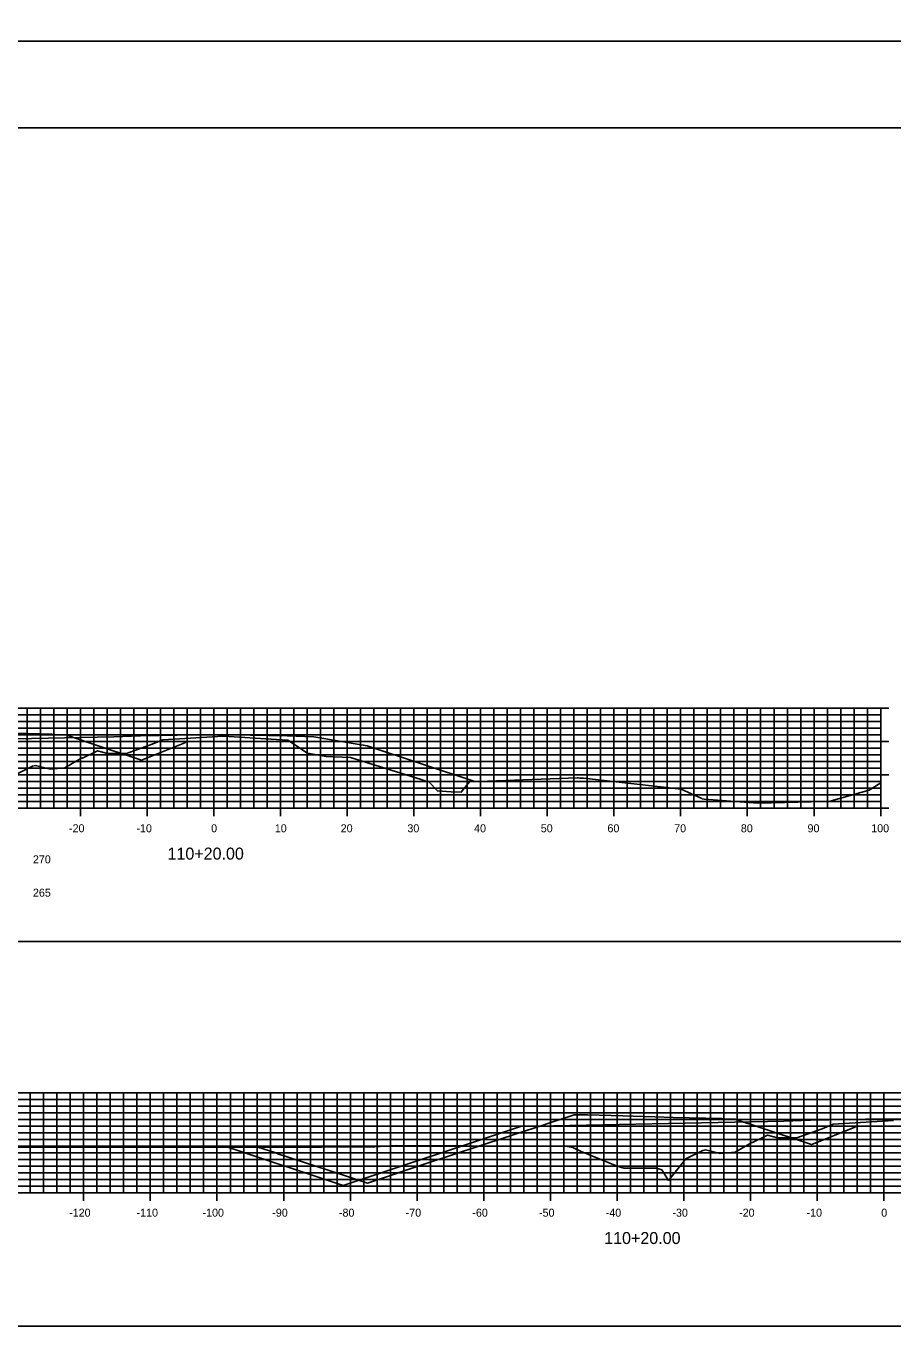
# Model space of a CAD drawing. Extents: x 1661012 to 1662122, y 670053 to 671852.
# Drawn here: x 1661778.9 to 1661908.9, y 671480 to 671675 of the extents above; entities that cross this region are included whole.
import ezdxf

# ---------------------------------------------------------------- set-up
doc = ezdxf.new("R2010")
doc.units = 0
for name, color, linetype in [('R_Concrete', 7, 'Continuous'), ('R_Concrete Hidden', 7, 'Continuous'), ('R_Erosion', 7, 'Continuous'), ('R_Exist Surface', 7, 'Continuous'), ('R_Proposed Road', 7, 'Continuous'), ('R_ROW Annot', 7, 'Continuous')]:
    doc.layers.add(name, color=color, linetype=linetype)

msp = doc.modelspace()

# ---------------------------------------------------------------- linework, layer by layer
at = {"layer": 'R_Concrete'}
for p, q in [((1661707.02, 671572.62), (1661907.02, 671572.62)), ((1661707.02, 671571.62), (1661907.02, 671571.62)), ((1661779.02, 671557.62), (1661779.02, 671572.62)), ((1661781.02, 671557.62), (1661781.02, 671572.62)), ((1661783.02, 671557.62), (1661783.02, 671572.62)), ((1661785.02, 671557.62), (1661785.02, 671572.62)), ((1661787.02, 671557.62), (1661787.02, 671572.62)), ((1661789.02, 671557.62), (1661789.02, 671572.62)), ((1661791.02, 671557.62), (1661791.02, 671572.62)), ((1661793.02, 671557.62), (1661793.02, 671572.62)), ((1661795.02, 671557.62), (1661795.02, 671572.62)), ((1661797.02, 671557.62), (1661797.02, 671572.62)), ((1661799.02, 671557.62), (1661799.02, 671572.62)), ((1661801.02, 671557.62), (1661801.02, 671572.62)), ((1661803.02, 671557.62), (1661803.02, 671572.62)), ((1661805.02, 671557.62), (1661805.02, 671572.62)), ((1661807.02, 671557.62), (1661807.02, 671572.62)), ((1661809.02, 671557.62), (1661809.02, 671572.62)), ((1661811.02, 671557.62), (1661811.02, 671572.62)), ((1661813.02, 671557.62), (1661813.02, 671572.62)), ((1661815.02, 671557.62), (1661815.02, 671572.62)), ((1661817.02, 671557.62), (1661817.02, 671572.62)), ((1661819.02, 671557.62), (1661819.02, 671572.62)), ((1661821.02, 671557.62), (1661821.02, 671572.62)), ((1661823.02, 671557.62), (1661823.02, 671572.62)), ((1661825.02, 671557.62), (1661825.02, 671572.62)), ((1661827.02, 671557.62), (1661827.02, 671572.62)), ((1661829.02, 671557.62), (1661829.02, 671572.62)), ((1661831.02, 671557.62), (1661831.02, 671572.62)), ((1661833.02, 671557.62), (1661833.02, 671572.62)), ((1661835.02, 671557.62), (1661835.02, 671572.62)), ((1661837.02, 671557.62), (1661837.02, 671572.62)), ((1661839.02, 671557.62), (1661839.02, 671572.62)), ((1661841.02, 671557.62), (1661841.02, 671572.62)), ((1661843.02, 671557.62), (1661843.02, 671572.62)), ((1661845.02, 671557.62), (1661845.02, 671572.62)), ((1661847.02, 671557.62), (1661847.02, 671572.62)), ((1661849.02, 671557.62), (1661849.02, 671572.62)), ((1661851.02, 671557.62), (1661851.02, 671572.62)), ((1661853.02, 671557.62), (1661853.02, 671572.62)), ((1661855.02, 671557.62), (1661855.02, 671572.62)), ((1661857.02, 671557.62), (1661857.02, 671572.62)), ((1661859.02, 671557.62), (1661859.02, 671572.62)), ((1661861.02, 671557.62), (1661861.02, 671572.62)), ((1661863.02, 671557.62), (1661863.02, 671572.62)), ((1661865.02, 671557.62), (1661865.02, 671572.62)), ((1661867.02, 671557.62), (1661867.02, 671572.62)), ((1661869.02, 671557.62), (1661869.02, 671572.62)), ((1661871.02, 671557.62), (1661871.02, 671572.62)), ((1661873.02, 671557.62), (1661873.02, 671572.62)), ((1661875.02, 671557.62), (1661875.02, 671572.62)), ((1661877.02, 671557.62), (1661877.02, 671572.62)), ((1661879.02, 671557.62), (1661879.02, 671572.62)), ((1661881.02, 671557.62), (1661881.02, 671572.62)), ((1661883.02, 671557.62), (1661883.02, 671572.62)), ((1661885.02, 671557.62), (1661885.02, 671572.62)), ((1661887.02, 671557.62), (1661887.02, 671572.62)), ((1661889.02, 671557.62), (1661889.02, 671572.62)), ((1661891.02, 671557.62), (1661891.02, 671572.62)), ((1661893.02, 671557.62), (1661893.02, 671572.62)), ((1661895.02, 671557.62), (1661895.02, 671572.62)), ((1661897.02, 671557.62), (1661897.02, 671572.62)), ((1661899.02, 671557.62), (1661899.02, 671572.62)), ((1661901.02, 671557.62), (1661901.02, 671572.62)), ((1661903.02, 671557.62), (1661903.02, 671572.62)), ((1661905.02, 671557.62), (1661905.02, 671572.62)), ((1661908.22, 671572.62), (1661905.82, 671572.62)), ((1661907.02, 671571.62), (1661906.42, 671571.62)), ((1661907.02, 671557.62), (1661907.02, 671572.62)), ((1661707.02, 671570.62), (1661907.02, 671570.62)), ((1661707.02, 671569.62), (1661907.02, 671569.62)), ((1661907.02, 671570.62), (1661906.42, 671570.62)), ((1661907.02, 671569.62), (1661906.42, 671569.62)), ((1661707.02, 671568.62), (1661907.02, 671568.62)), ((1661707.02, 671567.62), (1661907.02, 671567.62)), ((1661908.22, 671567.62), (1661905.82, 671567.62)), ((1661907.02, 671568.62), (1661906.42, 671568.62)), ((1661707.02, 671566.62), (1661907.02, 671566.62)), ((1661707.02, 671565.62), (1661907.02, 671565.62)), ((1661907.02, 671566.62), (1661906.42, 671566.62)), ((1661907.02, 671565.62), (1661906.42, 671565.62)), ((1661707.02, 671564.62), (1661907.02, 671564.62)), ((1661707.02, 671563.62), (1661907.02, 671563.62)), ((1661907.02, 671564.62), (1661906.42, 671564.62)), ((1661907.02, 671563.62), (1661906.42, 671563.62)), ((1661707.02, 671562.62), (1661907.02, 671562.62)), ((1661707.02, 671561.62), (1661907.02, 671561.62)), ((1661908.22, 671562.62), (1661905.82, 671562.62)), ((1661907.02, 671561.62), (1661906.42, 671561.62)), ((1661707.02, 671560.62), (1661907.02, 671560.62)), ((1661707.02, 671559.62), (1661907.02, 671559.62)), ((1661907.02, 671560.62), (1661906.42, 671560.62)), ((1661907.02, 671559.62), (1661906.42, 671559.62)), ((1661707.02, 671558.62), (1661907.02, 671558.62)), ((1661707.02, 671557.62), (1661907.02, 671557.62)), ((1661779.02, 671557.62), (1661779.02, 671558.22)), ((1661781.02, 671557.62), (1661781.02, 671558.22)), ((1661783.02, 671557.62), (1661783.02, 671558.22)), ((1661785.02, 671557.62), (1661785.02, 671558.22)), ((1661787.02, 671556.42), (1661787.02, 671558.82)), ((1661789.02, 671557.62), (1661789.02, 671558.22)), ((1661791.02, 671557.62), (1661791.02, 671558.22)), ((1661793.02, 671557.62), (1661793.02, 671558.22)), ((1661795.02, 671557.62), (1661795.02, 671558.22)), ((1661797.02, 671556.42), (1661797.02, 671558.82)), ((1661799.02, 671557.62), (1661799.02, 671558.22)), ((1661801.02, 671557.62), (1661801.02, 671558.22)), ((1661803.02, 671557.62), (1661803.02, 671558.22)), ((1661805.02, 671557.62), (1661805.02, 671558.22)), ((1661807.02, 671556.42), (1661807.02, 671558.82)), ((1661809.02, 671557.62), (1661809.02, 671558.22)), ((1661811.02, 671557.62), (1661811.02, 671558.22)), ((1661813.02, 671557.62), (1661813.02, 671558.22)), ((1661815.02, 671557.62), (1661815.02, 671558.22)), ((1661817.02, 671556.42), (1661817.02, 671558.82)), ((1661819.02, 671557.62), (1661819.02, 671558.22)), ((1661821.02, 671557.62), (1661821.02, 671558.22)), ((1661823.02, 671557.62), (1661823.02, 671558.22)), ((1661825.02, 671557.62), (1661825.02, 671558.22)), ((1661827.02, 671556.42), (1661827.02, 671558.82)), ((1661829.02, 671557.62), (1661829.02, 671558.22)), ((1661831.02, 671557.62), (1661831.02, 671558.22)), ((1661833.02, 671557.62), (1661833.02, 671558.22)), ((1661835.02, 671557.62), (1661835.02, 671558.22)), ((1661837.02, 671556.42), (1661837.02, 671558.82)), ((1661839.02, 671557.62), (1661839.02, 671558.22)), ((1661841.02, 671557.62), (1661841.02, 671558.22)), ((1661843.02, 671557.62), (1661843.02, 671558.22)), ((1661845.02, 671557.62), (1661845.02, 671558.22)), ((1661847.02, 671556.42), (1661847.02, 671558.82)), ((1661849.02, 671557.62), (1661849.02, 671558.22)), ((1661851.02, 671557.62), (1661851.02, 671558.22)), ((1661853.02, 671557.62), (1661853.02, 671558.22)), ((1661855.02, 671557.62), (1661855.02, 671558.22)), ((1661857.02, 671556.42), (1661857.02, 671558.82)), ((1661859.02, 671557.62), (1661859.02, 671558.22)), ((1661861.02, 671557.62), (1661861.02, 671558.22)), ((1661863.02, 671557.62), (1661863.02, 671558.22)), ((1661865.02, 671557.62), (1661865.02, 671558.22)), ((1661867.02, 671556.42), (1661867.02, 671558.82)), ((1661869.02, 671557.62), (1661869.02, 671558.22)), ((1661871.02, 671557.62), (1661871.02, 671558.22)), ((1661873.02, 671557.62), (1661873.02, 671558.22)), ((1661875.02, 671557.62), (1661875.02, 671558.22)), ((1661877.02, 671556.42), (1661877.02, 671558.82)), ((1661879.02, 671557.62), (1661879.02, 671558.22)), ((1661881.02, 671557.62), (1661881.02, 671558.22)), ((1661883.02, 671557.62), (1661883.02, 671558.22)), ((1661885.02, 671557.62), (1661885.02, 671558.22)), ((1661887.02, 671556.42), (1661887.02, 671558.82)), ((1661889.02, 671557.62), (1661889.02, 671558.22)), ((1661891.02, 671557.62), (1661891.02, 671558.22)), ((1661893.02, 671557.62), (1661893.02, 671558.22)), ((1661895.02, 671557.62), (1661895.02, 671558.22)), ((1661897.02, 671556.42), (1661897.02, 671558.82)), ((1661899.02, 671557.62), (1661899.02, 671558.22)), ((1661901.02, 671557.62), (1661901.02, 671558.22)), ((1661903.02, 671557.62), (1661903.02, 671558.22)), ((1661905.02, 671557.62), (1661905.02, 671558.22)), ((1661908.22, 671557.62), (1661905.82, 671557.62)), ((1661907.02, 671558.62), (1661906.42, 671558.62)), ((1661907.02, 671556.42), (1661907.02, 671558.82)), ((1661707.5, 671514.96), (1662037.5, 671514.96)), ((1661779.5, 671499.96), (1661779.5, 671514.96)), ((1661781.5, 671499.96), (1661781.5, 671514.96)), ((1661783.5, 671499.96), (1661783.5, 671514.96)), ((1661785.5, 671499.96), (1661785.5, 671514.96)), ((1661787.5, 671499.96), (1661787.5, 671514.96)), ((1661789.5, 671499.96), (1661789.5, 671514.96)), ((1661791.5, 671499.96), (1661791.5, 671514.96)), ((1661793.5, 671499.96), (1661793.5, 671514.96)), ((1661795.5, 671499.96), (1661795.5, 671514.96)), ((1661797.5, 671499.96), (1661797.5, 671514.96)), ((1661799.5, 671499.96), (1661799.5, 671514.96)), ((1661801.5, 671499.96), (1661801.5, 671514.96)), ((1661803.5, 671499.96), (1661803.5, 671514.96)), ((1661805.5, 671499.96), (1661805.5, 671514.96)), ((1661807.5, 671499.96), (1661807.5, 671514.96)), ((1661809.5, 671499.96), (1661809.5, 671514.96)), ((1661811.5, 671499.96), (1661811.5, 671514.96)), ((1661813.5, 671499.96), (1661813.5, 671514.96)), ((1661815.5, 671499.96), (1661815.5, 671514.96)), ((1661817.5, 671499.96), (1661817.5, 671514.96)), ((1661819.5, 671499.96), (1661819.5, 671514.96)), ((1661821.5, 671499.96), (1661821.5, 671514.96)), ((1661823.5, 671499.96), (1661823.5, 671514.96)), ((1661825.5, 671499.96), (1661825.5, 671514.96)), ((1661827.5, 671499.96), (1661827.5, 671514.96)), ((1661829.5, 671499.96), (1661829.5, 671514.96)), ((1661831.5, 671499.96), (1661831.5, 671514.96)), ((1661833.5, 671499.96), (1661833.5, 671514.96)), ((1661835.5, 671499.96), (1661835.5, 671514.96)), ((1661837.5, 671499.96), (1661837.5, 671514.96)), ((1661839.5, 671499.96), (1661839.5, 671514.96)), ((1661841.5, 671499.96), (1661841.5, 671514.96)), ((1661843.5, 671499.96), (1661843.5, 671514.96)), ((1661845.5, 671499.96), (1661845.5, 671514.96)), ((1661847.5, 671499.96), (1661847.5, 671514.96)), ((1661849.5, 671499.96), (1661849.5, 671514.96)), ((1661851.5, 671499.96), (1661851.5, 671514.96)), ((1661853.5, 671499.96), (1661853.5, 671514.96)), ((1661855.5, 671499.96), (1661855.5, 671514.96)), ((1661857.5, 671499.96), (1661857.5, 671514.96)), ((1661859.5, 671499.96), (1661859.5, 671514.96)), ((1661861.5, 671499.96), (1661861.5, 671514.96)), ((1661863.5, 671499.96), (1661863.5, 671514.96)), ((1661865.5, 671499.96), (1661865.5, 671514.96)), ((1661867.5, 671499.96), (1661867.5, 671514.96)), ((1661869.5, 671499.96), (1661869.5, 671514.96)), ((1661871.5, 671499.96), (1661871.5, 671514.96)), ((1661873.5, 671499.96), (1661873.5, 671514.96)), ((1661875.5, 671499.96), (1661875.5, 671514.96)), ((1661877.5, 671499.96), (1661877.5, 671514.96)), ((1661879.5, 671499.96), (1661879.5, 671514.96)), ((1661881.5, 671499.96), (1661881.5, 671514.96)), ((1661883.5, 671499.96), (1661883.5, 671514.96)), ((1661885.5, 671499.96), (1661885.5, 671514.96)), ((1661887.5, 671499.96), (1661887.5, 671514.96)), ((1661889.5, 671499.96), (1661889.5, 671514.96)), ((1661891.5, 671499.96), (1661891.5, 671514.96)), ((1661893.5, 671499.96), (1661893.5, 671514.96)), ((1661895.5, 671499.96), (1661895.5, 671514.96)), ((1661897.5, 671499.96), (1661897.5, 671514.96)), ((1661899.5, 671499.96), (1661899.5, 671514.96)), ((1661901.5, 671499.96), (1661901.5, 671514.96)), ((1661903.5, 671499.96), (1661903.5, 671514.96)), ((1661905.5, 671499.96), (1661905.5, 671514.96)), ((1661907.5, 671499.96), (1661907.5, 671514.96)), ((1661707.5, 671513.96), (1662037.5, 671513.96)), ((1661707.5, 671512.96), (1662037.5, 671512.96)), ((1661707.5, 671511.96), (1662037.5, 671511.96)), ((1661707.5, 671510.96), (1662037.5, 671510.96)), ((1661707.5, 671509.96), (1662037.5, 671509.96)), ((1661707.5, 671508.96), (1662037.5, 671508.96)), ((1661707.5, 671507.96), (1662037.5, 671507.96)), ((1661707.5, 671506.96), (1662037.5, 671506.96)), ((1661707.5, 671505.96), (1662037.5, 671505.96)), ((1661707.5, 671504.96), (1662037.5, 671504.96)), ((1661707.5, 671503.96), (1662037.5, 671503.96)), ((1661707.5, 671502.96), (1662037.5, 671502.96)), ((1661707.5, 671501.96), (1662037.5, 671501.96)), ((1661707.5, 671500.96), (1662037.5, 671500.96)), ((1661779.5, 671499.96), (1661779.5, 671500.56)), ((1661781.5, 671499.96), (1661781.5, 671500.56)), ((1661783.5, 671499.96), (1661783.5, 671500.56)), ((1661785.5, 671499.96), (1661785.5, 671500.56)), ((1661787.5, 671498.76), (1661787.5, 671501.16)), ((1661789.5, 671499.96), (1661789.5, 671500.56)), ((1661791.5, 671499.96), (1661791.5, 671500.56)), ((1661793.5, 671499.96), (1661793.5, 671500.56)), ((1661795.5, 671499.96), (1661795.5, 671500.56)), ((1661797.5, 671498.76), (1661797.5, 671501.16)), ((1661799.5, 671499.96), (1661799.5, 671500.56)), ((1661801.5, 671499.96), (1661801.5, 671500.56)), ((1661803.5, 671499.96), (1661803.5, 671500.56)), ((1661805.5, 671499.96), (1661805.5, 671500.56)), ((1661807.5, 671498.76), (1661807.5, 671501.16)), ((1661809.5, 671499.96), (1661809.5, 671500.56)), ((1661811.5, 671499.96), (1661811.5, 671500.56)), ((1661813.5, 671499.96), (1661813.5, 671500.56)), ((1661815.5, 671499.96), (1661815.5, 671500.56)), ((1661817.5, 671498.76), (1661817.5, 671501.16)), ((1661819.5, 671499.96), (1661819.5, 671500.56)), ((1661821.5, 671499.96), (1661821.5, 671500.56)), ((1661823.5, 671499.96), (1661823.5, 671500.56)), ((1661825.5, 671499.96), (1661825.5, 671500.56)), ((1661827.5, 671498.76), (1661827.5, 671501.16)), ((1661829.5, 671499.96), (1661829.5, 671500.56)), ((1661831.5, 671499.96), (1661831.5, 671500.56)), ((1661833.5, 671499.96), (1661833.5, 671500.56)), ((1661835.5, 671499.96), (1661835.5, 671500.56)), ((1661837.5, 671498.76), (1661837.5, 671501.16)), ((1661839.5, 671499.96), (1661839.5, 671500.56)), ((1661841.5, 671499.96), (1661841.5, 671500.56)), ((1661843.5, 671499.96), (1661843.5, 671500.56)), ((1661845.5, 671499.96), (1661845.5, 671500.56)), ((1661847.5, 671498.76), (1661847.5, 671501.16)), ((1661849.5, 671499.96), (1661849.5, 671500.56)), ((1661851.5, 671499.96), (1661851.5, 671500.56)), ((1661853.5, 671499.96), (1661853.5, 671500.56)), ((1661855.5, 671499.96), (1661855.5, 671500.56)), ((1661857.5, 671498.76), (1661857.5, 671501.16)), ((1661859.5, 671499.96), (1661859.5, 671500.56)), ((1661861.5, 671499.96), (1661861.5, 671500.56)), ((1661863.5, 671499.96), (1661863.5, 671500.56)), ((1661865.5, 671499.96), (1661865.5, 671500.56)), ((1661867.5, 671498.76), (1661867.5, 671501.16)), ((1661869.5, 671499.96), (1661869.5, 671500.56)), ((1661871.5, 671499.96), (1661871.5, 671500.56)), ((1661873.5, 671499.96), (1661873.5, 671500.56)), ((1661875.5, 671499.96), (1661875.5, 671500.56)), ((1661877.5, 671498.76), (1661877.5, 671501.16)), ((1661879.5, 671499.96), (1661879.5, 671500.56)), ((1661881.5, 671499.96), (1661881.5, 671500.56)), ((1661883.5, 671499.96), (1661883.5, 671500.56)), ((1661885.5, 671499.96), (1661885.5, 671500.56)), ((1661887.5, 671498.76), (1661887.5, 671501.16)), ((1661889.5, 671499.96), (1661889.5, 671500.56)), ((1661891.5, 671499.96), (1661891.5, 671500.56)), ((1661893.5, 671499.96), (1661893.5, 671500.56)), ((1661895.5, 671499.96), (1661895.5, 671500.56)), ((1661897.5, 671498.76), (1661897.5, 671501.16)), ((1661899.5, 671499.96), (1661899.5, 671500.56)), ((1661901.5, 671499.96), (1661901.5, 671500.56)), ((1661903.5, 671499.96), (1661903.5, 671500.56)), ((1661905.5, 671499.96), (1661905.5, 671500.56)), ((1661907.5, 671498.76), (1661907.5, 671501.16)), ((1661707.5, 671499.96), (1662037.5, 671499.96))]:
    msp.add_line(p, q, dxfattribs=at)
at = {"layer": 'R_Erosion'}
for points in [[(1661777.32, 671562.7), (1661779.85, 671563.96), (1661780.28, 671564.03), (1661782.47, 671563.49), (1661784.7, 671563.71), (1661787.23, 671565.17), (1661787.32, 671565.16), (1661789.56, 671566.25), (1661791.09, 671565.85), (1661793.94, 671565.85), (1661797.79, 671567.22), (1661799.4, 671567.9), (1661808.46, 671568.46), (1661816.44, 671567.94), (1661818.14, 671567.82), (1661821.05, 671565.89), (1661823.86, 671565.41), (1661827.47, 671565.25), (1661827.5, 671565.23), (1661838.1, 671561.92), (1661838.93, 671561.65), (1661839.23, 671561.58), (1661839.24, 671561.57), (1661840.56, 671560.23), (1661842.63, 671560.11), (1661844.12, 671560.06), (1661844.93, 671561.03), (1661845.38, 671561.6), (1661861.51, 671562.19), (1661861.65, 671562.21), (1661861.93, 671562.16), (1661862.47, 671562.13), (1661877.08, 671560.49), (1661880.18, 671559.07), (1661880.25, 671559.03), (1661880.53, 671559.01), (1661888.61, 671558.39), (1661898.61, 671558.64), (1661899.28, 671558.66), (1661899.95, 671558.83), (1661905.27, 671560.32), (1661907.02, 671561.44)], [(1661767.07, 671506.79), (1661782.62, 671506.79), (1661791.52, 671506.8), (1661800.94, 671506.8), (1661814.49, 671506.8), (1661823.2, 671506.8), (1661831.18, 671506.86), (1661834.38, 671507.04), (1661855.17, 671506.94), (1661859.78, 671506.94), (1661860.88, 671506.74), (1661862.12, 671506.14), (1661867.51, 671503.95), (1661868.5, 671503.63), (1661873.42, 671503.64), (1661874.19, 671503.4), (1661875.2, 671501.81), (1661877.79, 671505.04), (1661880.33, 671506.3), (1661880.75, 671506.37), (1661882.94, 671505.83), (1661885.18, 671506.05), (1661887.71, 671507.51), (1661887.79, 671507.5), (1661890.03, 671508.59), (1661891.56, 671508.19), (1661894.42, 671508.19), (1661898.26, 671509.55), (1661899.87, 671510.24), (1661908.94, 671510.8)]]:
    msp.add_lwpolyline(points, dxfattribs=at)
at = {"layer": 'R_Exist Surface'}
for p, q in [((1661907.02, 671557.62), (1661907.02, 671572.62)), ((1661707.02, 671557.62), (1661907.02, 671557.62)), ((1661707.5, 671499.96), (1662037.5, 671499.96))]:
    msp.add_line(p, q, dxfattribs=at)
at = {"layer": 'R_Proposed Road'}
for points in [[(1661756.99, 671659.7), (1662116.99, 671659.7), (1662116.99, 671852.4), (1661756.99, 671852.4)], [(1661677.02, 671537.62), (1662037.02, 671537.62), (1662037.02, 671730.32), (1661677.02, 671730.32)], [(1661677.5, 671479.96), (1662037.5, 671479.96), (1662037.5, 671672.66), (1661677.5, 671672.66)]]:
    msp.add_lwpolyline(points, close=True, dxfattribs=at)
at = {"layer": 'R_ROW Annot'}
for points in [[(1661775.41, 671568.92), (1661782.71, 671568.73), (1661782.74, 671568.73), (1661783.17, 671568.71), (1661784.73, 671568.65), (1661784.98, 671568.57), (1661788.47, 671567.41), (1661790.14, 671566.86), (1661794.81, 671565.31), (1661796.17, 671564.86), (1661796.19, 671564.85), (1661802.66, 671567.46), (1661802.81, 671567.55)], [(1661708.63, 671564.46), (1661725.96, 671558.68), (1661752.52, 671567.54), (1661784.62, 671568.18), (1661792.02, 671568.33), (1661796.02, 671568.49), (1661807.02, 671568.71), (1661818.02, 671568.49), (1661822.02, 671568.33), (1661829.43, 671567.1), (1661830.02, 671567), (1661846.15, 671561.62)], [(1661809.1, 671506.8), (1661826.43, 671501.02), (1661853, 671509.88), (1661885.09, 671510.52), (1661892.5, 671510.67), (1661896.5, 671510.83), (1661907.5, 671511.05), (1661918.5, 671510.83), (1661922.5, 671510.67), (1661929.91, 671509.43), (1661930.5, 671509.34), (1661946.62, 671503.96)], [(1661813.63, 671506.8), (1661816.16, 671505.97), (1661816.64, 671505.81), (1661826.15, 671502.68), (1661830.05, 671501.4), (1661838.88, 671504.32), (1661850.99, 671508.32), (1661851.21, 671508.39), (1661852.36, 671508.77), (1661856.41, 671510.11), (1661857.13, 671510.35), (1661860.16, 671511.35), (1661861.05, 671511.64), (1661861.61, 671511.64), (1661863.06, 671511.62), (1661868.33, 671511.47), (1661873.13, 671511.34), (1661875.89, 671511.26), (1661883.19, 671511.07), (1661883.22, 671511.07), (1661883.64, 671511.05), (1661885.2, 671510.99), (1661885.45, 671510.91), (1661888.94, 671509.75), (1661890.62, 671509.2), (1661895.28, 671507.65), (1661896.64, 671507.2), (1661896.67, 671507.19), (1661903.13, 671509.8), (1661903.28, 671509.89)]]:
    msp.add_lwpolyline(points, dxfattribs=at)

# ---------------------------------------------------------------- texts
at = {"layer": 'R_Concrete Hidden'}
for s, height, p in [('-20', 1.2, (1661785.31, 671554.02)), ('-10', 1.2, (1661795.42, 671554.02)), ('0', 1.2, (1661806.62, 671554.02)), ('10', 1.2, (1661816.17, 671554.02)), ('20', 1.2, (1661826.05, 671554.02)), ('30', 1.2, (1661836.05, 671554.02)), ('40', 1.2, (1661846.05, 671554.02)), ('50', 1.2, (1661856.05, 671554.02)), ('60', 1.2, (1661866.05, 671554.02)), ('70', 1.2, (1661876.05, 671554.02)), ('80', 1.2, (1661886.05, 671554.02)), ('90', 1.2, (1661896.05, 671554.02)), ('100', 1.2, (1661905.6, 671554.02)), ('110+20.00', 1.8, (1661800.08, 671549.92)), ('270', 1.2, (1661779.9, 671549.36)), ('265', 1.2, (1661779.9, 671544.36)), ('-120', 1.2, (1661785.33, 671496.36)), ('-110', 1.2, (1661795.44, 671496.36)), ('-100', 1.2, (1661805.33, 671496.36)), ('-90', 1.2, (1661815.79, 671496.36)), ('-80', 1.2, (1661825.79, 671496.36)), ('-70', 1.2, (1661835.79, 671496.36)), ('-60', 1.2, (1661845.79, 671496.36)), ('-50', 1.2, (1661855.79, 671496.36)), ('-40', 1.2, (1661865.79, 671496.36)), ('-30', 1.2, (1661875.79, 671496.36)), ('-20', 1.2, (1661885.79, 671496.36)), ('-10', 1.2, (1661895.9, 671496.36)), ('0', 1.2, (1661907.1, 671496.36)), ('110+20.00', 1.8, (1661865.56, 671492.26))]:
    msp.add_text(s, height=height, dxfattribs=at).set_placement(p)

doc.saveas('drawing.dxf')
